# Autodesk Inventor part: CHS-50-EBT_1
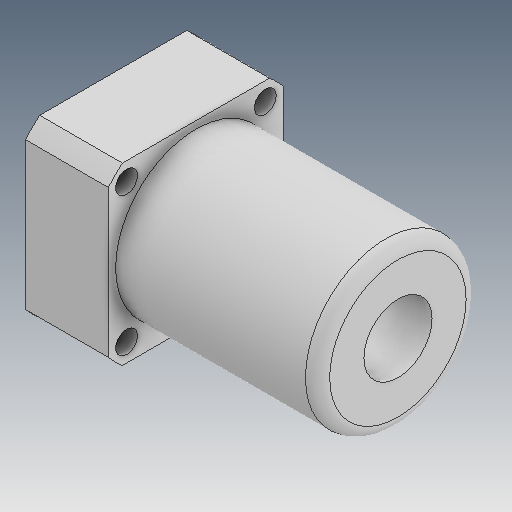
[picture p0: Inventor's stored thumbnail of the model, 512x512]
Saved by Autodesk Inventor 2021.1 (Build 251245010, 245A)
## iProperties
Created: 2019-04
Part Number: CHS-50-EBT_1
Material: Ogólny
Document SubType Name: Modeling
Designer: user
Density: 1 g/cm^3
Appearance: Domyślna
Author: user
Revision Number: ÈÎºÎ
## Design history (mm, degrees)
feature "ÊäÈë1"
node "Bryła1"
